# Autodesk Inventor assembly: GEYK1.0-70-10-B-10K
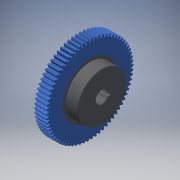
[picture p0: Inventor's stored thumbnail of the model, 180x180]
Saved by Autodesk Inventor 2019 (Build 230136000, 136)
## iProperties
Category: PARTsolutions
Company: MISUMI
Created: 2022-11
Part Number: GEYK1.0-70-10-B-10K
Catalog Web Link: www.cadenas.de
Description: GEY_-Plastic Bonded Spur Gears
Vendor: MISUMI
Document SubType Name: Assembly
Designer: psAdmin
Manufacturer: MISUMI
Mass: 49.0279 g
Surface Area: 167.17 cm^2
Volume: 49.0279 cm^3
Density: 1 g/cm^3
Title: GEYK1.0-70-10-B-10K
Author: Cadenas PARTsolutions
Comments: Plastic Bonded Spur Gears
PSOL_IDENT_0: {$CADENAS_DATA/23d-libs/misumi/metric/54_spur_gears/gey_asmtab.prj},217 {VTYP=3D},{STYP=ASSTAB},{NB=
PSOL_IDENT_1: GEYK1.0-70-10-B-10K},{LINA=GEYK1.0-70-10-B-10K},{NN=GEY_},{DATE=07.06.2021 01:25:59},{GEOMDATE=22.08
PSOL_IDENT_2: .2016 06:34:21},{VERSION=},{LINEID=10},{WBVAR=SHS,NT,PS,ALT1,ALT2,BS},{WBNUMERIC=NT,BS}  {NB=GEYK1.0
PSOL_IDENT_3: -70-10-B-10K},{LINA=GEYK1.0-70-10-B-10K},{KT=DUMMY},{PN=GEYK1.0-70-10-B-10K},{SHS=K},{SHSPN=K},{GEAK
PSOL_IDENT_4: BH=0},{MAT=MC Nylon},{MATC=S25C},{AC=Set Screw},{MOD=1.0},{NT=70},{NTA=30,32,34,35,36,38,40,42,45,48
PSOL_IDENT_5: ,50,52,56,60,70,75},{B=10},{TS=B},{TSA='B','B'},{PS=10K},{PSA= '10N','10N','10K','10K','11N','11N','
PSOL_IDENT_6: 12N','12N','13N','13N','14N','14N','15N','15N','16N','16N','17N','17N','18N','18N','19N','19N','20N'
PSOL_IDENT_7: ,'20N','21N','21N','22N','22N','23N','23N','24N','24N'},{PS1= '10','10','11','11','12','12','13','13'
PSOL_IDENT_8: ,'14','14','15','15','16','16','17','17','18','18','19','19','20','20','21','21','22','22','23','23'
PSOL_IDENT_9: ,'24','24','25','25','26','26','27','27','28','28'},{PS2= '10N','10N','10K','10K','11N','11N','12N','
PSOL_IDENT_10: 12N','13N','13N','14N','14N','15N','15N','16N','16N','17N','17N','18N','18N','19N','19N','20N','20N'
PSOL_IDENT_11: ,'21N','21N','22N','22N','23N','23N','24N','24N'},{P=10.00},{DD=70.0},{D=72.0},{H=40},{E=45},{L=20},
PSOL_IDENT_12: {LL=10},{LL2=5.000},{M=M4},{M2=4},{ACSS=M4x3},{TT=1.8},{BB=4},{ALT1=},{ALTA='','w/o Set Screw', '-KC
PSOL_IDENT_13: 90', 'with KC90 (Set Screw)', '-KC120', 'with KC120 (Set Screw)'},{SCREWL=3},{PLANE=20},{PLANE1=20},
PSOL_IDENT_14: {ALT2=},{ALT2A='','w/o Boss Cut','-BS','with BS (Boss Cut)'},{BS=0.0},{BSA=0},{BSMIN=7.0},{BSMAX=9.5
PSOL_IDENT_15: },{HD=15.000},{PPATH=gey_asmtpl.prj}
NB: GEYK1.0-70-10-B-10K
NN: GEY_
NT: 70
NBSYN: $PN.
LINA: GEYK1.0-70-10-B-10K
CATALOG: Misumi
PN: GEYK1.0-70-10-B-10K
SHS: Key Groove Hole+Tap
MAT: MC Nylon
MATC: S25C
AC: Set Screw
MOD: 1.0
B: 10
TS: B
PS: 10K
DD: 70
D: 72
H: 40
E: 45
L: 20
LL: 10
M: M4
ALT1: w/o Set Screw
ALT2: w/o Boss Cut
BS: 0
SUPPLIER: MISUMI
ARTICLENO: GEYK1.0-70-10-B-10K
BOMINFO: GEYK1.0-70-10-B-10K
CREATOR: CADENAS GmbH
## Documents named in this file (4)
- e:\temp\worker_COMMON_6\temp\tmp_4032_386_yddUP\format_0\GEYK1_0-70-10-B-10K.iam
- e:\temp\worker_COMMON_6\temp\tmp_4032_386_yddUP\format_0\GEYK1_0-70-10-B-10K_0_b.ipt
- e:\temp\worker_COMMON_6\temp\tmp_4032_386_yddUP\format_0\Hexagon socket set screw with flat point DIN 913 - M4x3.ipt
- e:\temp\worker_COMMON_6\temp\tmp_4032_386_yddUP\format_0\GEYK1_0-70-10-B-10K_0_t.ipt
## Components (3 placed, 3 different names)
1. GEYK1_0-70-10-B-10K_0_b:1 — screw1_XY@1 <-> IP1_XY@2, screw1_Z@1 <-> IP1_Z@2, screw1_YZ@1 <-> IP1_YZ@2, body_to_teeth_XY@1 <-> teeth_to_body_XY@3, body_to_teeth_Z@1 <-> teeth_to_body_Z@3, body_to_teeth_YZ@1 <-> teeth_to_body_YZ@3
2. Hexagon socket set screw with flat point DIN 913 - M4x3:1 — screw1_XY@1 <-> IP1_XY@2, screw1_Z@1 <-> IP1_Z@2, screw1_YZ@1 <-> IP1_YZ@2
3. GEYK1_0-70-10-B-10K_0_t:1 — body_to_teeth_XY@1 <-> teeth_to_body_XY@3, body_to_teeth_Z@1 <-> teeth_to_body_Z@3, body_to_teeth_YZ@1 <-> teeth_to_body_YZ@3
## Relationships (6: Mate 3, Angle 2, Flush 1)
- screw1_XY@1 <-> IP1_XY@2 [Flush]: GEYK1_0-70-10-B-10K_0_b:1 ↔ Hexagon socket set screw with flat point DIN 913 - M4x3:1
- screw1_Z@1 <-> IP1_Z@2 [Mate]: GEYK1_0-70-10-B-10K_0_b:1 ↔ Hexagon socket set screw with flat point DIN 913 - M4x3:1
- screw1_YZ@1 <-> IP1_YZ@2 [Angle]: GEYK1_0-70-10-B-10K_0_b:1 ↔ Hexagon socket set screw with flat point DIN 913 - M4x3:1
- body_to_teeth_XY@1 <-> teeth_to_body_XY@3 [Mate]: GEYK1_0-70-10-B-10K_0_b:1 ↔ GEYK1_0-70-10-B-10K_0_t:1
- body_to_teeth_Z@1 <-> teeth_to_body_Z@3 [Mate]: GEYK1_0-70-10-B-10K_0_b:1 ↔ GEYK1_0-70-10-B-10K_0_t:1
- body_to_teeth_YZ@1 <-> teeth_to_body_YZ@3 [Angle]: GEYK1_0-70-10-B-10K_0_b:1 ↔ GEYK1_0-70-10-B-10K_0_t:1
